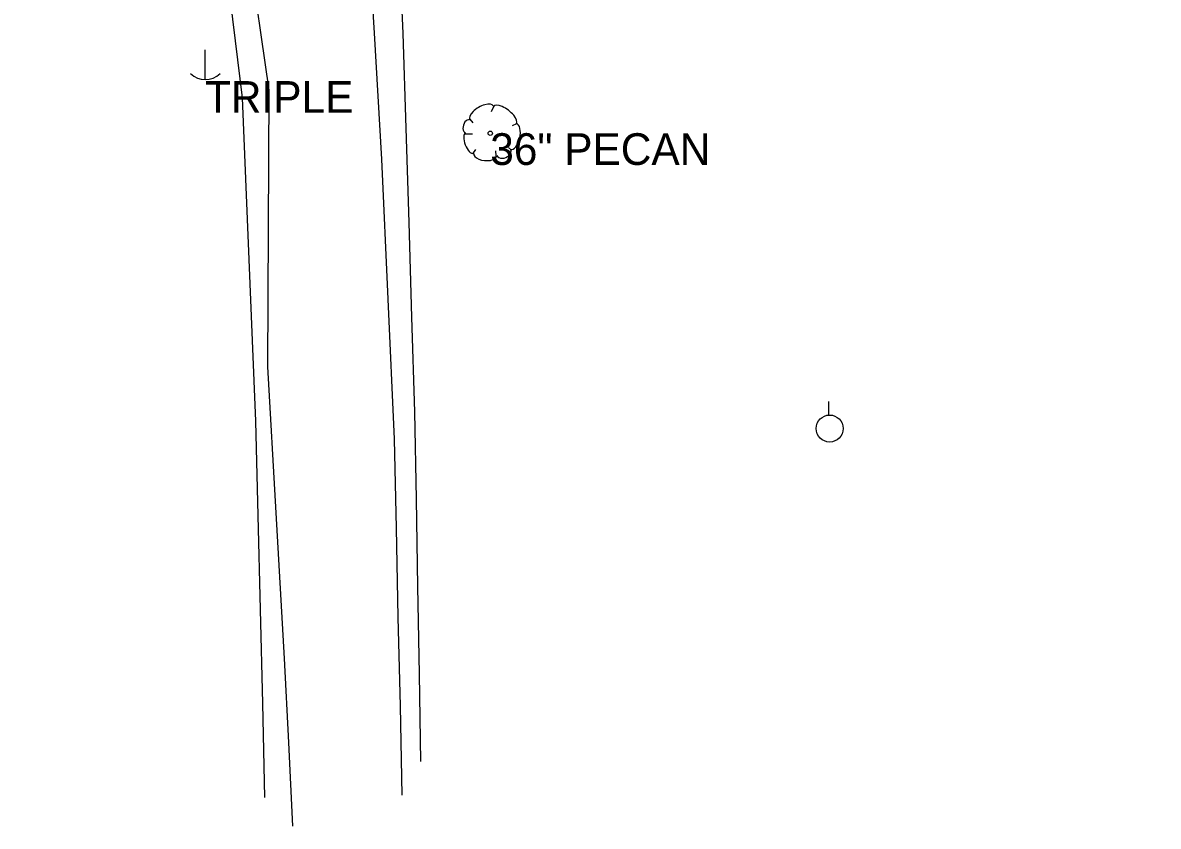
# Model space of a CAD drawing. Extents: x 1404740 to 1407214, y 1837339 to 1847120.
# Drawn here: x 1405702.8 to 1405881.9, y 1842127.2 to 1842254 of the extents above; entities that cross this region are included whole.
import ezdxf

# ---------------------------------------------------------------- set-up
doc = ezdxf.new("R2010")
doc.units = 0
for name, color, linetype in [('S_DITCHLINE', 7, 'Continuous'), ('S_GRAVEL_ROAD', 7, 'Continuous'), ('S_TREE', 7, 'Continuous'), ('S_TREE_ANNOT', 7, 'Continuous'), ('S_UTILITY_POLE', 7, 'Continuous'), ('S_UTILITY_POLE_ANNOT', 7, 'Continuous')]:
    doc.layers.add(name, color=color, linetype=linetype)

msp = doc.modelspace()

# ---------------------------------------------------------------- linework, layer by layer
at = {"layer": 'S_DITCHLINE'}
for points in [[(1405881.86, 1842451.53), (1405868.49, 1842437.35), (1405855.12, 1842423.17), (1405841.75, 1842408.98), (1405829.3, 1842395.5), (1405816.85, 1842382.01), (1405804.39, 1842368.53), (1405791.94, 1842355.04), (1405777.34, 1842337.89), (1405762.73, 1842320.75), (1405753.09, 1842310.52), (1405757.74, 1842304.75), (1405761.2, 1842285.84), (1405761.98, 1842269.07), (1405762.76, 1842252.3), (1405763.21, 1842237.38), (1405763.67, 1842222.46), (1405764.12, 1842207.55), (1405764.58, 1842192.63), (1405764.82, 1842178.84), (1405765.06, 1842165.05), (1405765.3, 1842151.25), (1405765.54, 1842137.46)], [(1405741, 1842131.76), (1405740.64, 1842146.6), (1405740.27, 1842161.44), (1405739.91, 1842176.28), (1405739.54, 1842191.12), (1405739.02, 1842203.87), (1405738.5, 1842216.62), (1405737.98, 1842229.38), (1405737.46, 1842242.13), (1405734.81, 1842263.59), (1405732.17, 1842285.05), (1405727.91, 1842292.7), (1405722.72, 1842289.93), (1405712.33, 1842282.74), (1405701.94, 1842275.54)]]:
    msp.add_lwpolyline(points, dxfattribs=at)
at = {"layer": 'S_GRAVEL_ROAD'}
for points in [[(1405749.39, 1842327.13), (1405748.57, 1842309.09), (1405752.79, 1842290.65), (1405757.02, 1842272.21), (1405758.2, 1842252.33), (1405759.38, 1842232.45), (1405760.37, 1842210.37), (1405761.35, 1842188.29), (1405761.66, 1842174.26), (1405761.97, 1842160.22), (1405762.29, 1842146.18), (1405762.6, 1842132.14)], [(1405707.43, 1842297.37), (1405728.64, 1842295.23), (1405735.16, 1842287.82), (1405738.4, 1842265.59), (1405741.63, 1842243.36), (1405741.5, 1842221.53), (1405741.37, 1842199.7), (1405742.7, 1842176.69), (1405744.04, 1842153.69), (1405744.69, 1842140.47), (1405745.35, 1842127.24)]]:
    msp.add_lwpolyline(points, dxfattribs=at)
at = {"layer": 'S_TREE'}
for p, q in [((1405777.08, 1842240.81), (1405776.69, 1842239.95)), ((1405773.28, 1842238.79), (1405773.78, 1842238.21)), ((1405780.64, 1842238.02), (1405779.98, 1842237.74)), ((1405772.62, 1842236.47), (1405773.74, 1842236.47)), ((1405773.78, 1842233.29), (1405774.25, 1842233.99)), ((1405777.46, 1842233.02), (1405777.39, 1842233.79)), ((1405779.87, 1842233.91), (1405779.4, 1842234.33))]:
    msp.add_line(p, q, dxfattribs=at)
msp.add_circle((1405776.52, 1842236.56), 0.341, dxfattribs=at)
for centre, major_axis, ratio, start_param, end_param in [((1405775.18, 1842239.76), (1.86, 1.08), 0.471018, 0, 3.141593), ((1405778.84, 1842239.44), (-1.81, 1.36), 0.405113, 3.141593, 6.283186), ((1405772.95, 1842237.65), (0.31, 1.03), 0.646762, 0, 3.141593), ((1405780.19, 1842236.03), (0.46, 2.04), 0.482994, 3.141593, 6.283185), ((1405773.25, 1842235), (-0.61, 1.6), 0.420543, 6.283185, 9.424777), ((1405778.67, 1842233.51), (1.09, 0.46), 0.711534, 3.141592, 6.283185), ((1405775.71, 1842233.22), (-1.83, 0.19), 0.529943, 0, 3.141593)]:
    msp.add_ellipse(centre, major_axis=major_axis, ratio=ratio, start_param=start_param, end_param=end_param, dxfattribs=at)
at = {"layer": 'S_UTILITY_POLE'}
for p, q in [((1405731.52, 1842249.73), (1405731.52, 1842245)), ((1405829.93, 1842192.12), (1405829.93, 1842194.23))]:
    msp.add_line(p, q, dxfattribs=at)
msp.add_circle((1405830.05, 1842189.98), 2.13, dxfattribs=at)
msp.add_arc((1405731.58, 1842248.43), 3.41, 226.3972, 313.6028, dxfattribs=at)

# ---------------------------------------------------------------- texts
at = {"layer": 'S_TREE_ANNOT'}
msp.add_text('36" PECAN', height=5, dxfattribs=at).set_placement((1405776.52, 1842231.56))
at = {"layer": 'S_UTILITY_POLE_ANNOT'}
msp.add_text('TRIPLE', height=5, dxfattribs=at).set_placement((1405731.53, 1842239.78))

doc.saveas('drawing.dxf')
